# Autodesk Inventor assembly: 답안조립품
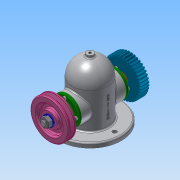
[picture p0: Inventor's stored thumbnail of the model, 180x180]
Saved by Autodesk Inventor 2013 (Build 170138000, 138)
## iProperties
Created: 2019-11
Part Number: 답안조립품
Document SubType Name: Assembly
Designer: Administrator
Author: Administrator
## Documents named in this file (14)
- C:\Users\Administrator\Desktop\491104V1040\답안조립품.iam
- C:\Users\Administrator\Desktop\491104V1040\본체.ipt
- C:\Users\Administrator\Desktop\491104V1040\V-벨트풀리.ipt
- V-벨트풀리.ipt
- C:\Users\Administrator\Desktop\491104V1040\너트 M12x1.25.ipt
- C:\Users\Administrator\Desktop\491104V1040\베어링 6203.ipt
- C:\Users\Administrator\Desktop\491104V1040\볼트 M4.ipt
- C:\Users\Administrator\Desktop\491104V1040\부시.ipt
- C:\Users\Administrator\Desktop\491104V1040\스퍼기어.ipt
- C:\Users\Administrator\Desktop\491104V1040\오일 실 26 38 8.ipt
- C:\Users\Administrator\Desktop\491104V1040\와셔 12x24.ipt
- C:\Users\Administrator\Desktop\491104V1040\축.ipt
- C:\Users\Administrator\Desktop\491104V1040\커버.ipt
- C:\Users\Administrator\Desktop\491104V1040\키 5x5x12.ipt
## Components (1 placed, 1 different names)
1. V-벨트풀리:1
